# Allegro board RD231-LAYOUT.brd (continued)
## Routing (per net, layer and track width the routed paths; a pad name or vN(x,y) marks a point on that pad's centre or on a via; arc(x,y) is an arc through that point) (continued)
VCC12: length 11.2
  TOP w0.35: IC9.9 38.09,88.65 38.11,88.64 ; 38.11,88.64 38.4,88.53 ; 38.11,88.64 38.22,88.34 ; 38.11,88.64 38.35,88.39
  TOP w0.635: C109.1 39.12,87.63 ; 39.12,87.63 38.35,88.39 ; 39.12,87.63 38.61,87.12 C110.2 R116.1 38.61,82.61 37.28,81.28
DRVCC: length 55.1
  CONDUCTIVE3 w0.635: 64.64,43.94 61.98,43.94 58.22,40.19 ; 64.64,43.94 66.36,42.22 ; 64.64,43.94 66.93,46.23 ; 65.69,54.43 65.29,55.09 ; 65.69,54.43 65.02,54.83 ; 65.69,54.43 v1(65.12,54.99) ; 65.69,54.43 66.93,53.19 66.93,46.23 ; 58.22,40.19 v1(57.66,39.62) ; 58.22,40.19 57.82,39.53 ; 58.22,40.19 57.56,39.79 ; 70.94,44.51 69.22,46.23 66.93,46.23 ; 70.94,44.51 71.6,44.1 ; 70.94,44.51 71.34,43.84 ; 70.94,44.51 v1(71.5,43.94) ; 66.36,42.22 v1(66.93,41.66) ; 66.36,42.22 66.77,41.56 ; 66.36,42.22 67.03,41.82
  BOTTOM w0.35: 65.12,54.38 65.3,54.94 ; 65.12,54.38 v1(65.12,54.99) ; 65.12,54.38 65.12,52.5 ; 65.12,54.38 64.95,54.94 ; 65.62,43.07 65.49,42.58 ; 65.62,43.07 65.62,44.02 ; 65.62,43.07 65.76,42.58 ; 65.62,43.07 65.62,42.55
  BOTTOM w0.635: 65.62,42.55 65.62,42.07 66.04,41.66 66.46,41.66 ; 67.26,41.33 66.96,41.68 ; 67.26,41.33 v1(66.93,41.66) 66.46,41.66 ; 67.26,41.33 66.9,41.63 ; 67.26,41.33 68.45,40.13 C5.1 ; 57.65,39.66 57.19,39.62 ; 57.19,39.62 57.65,39.59 ; 57.19,39.62 D1.1 ; 57.19,39.62 v1(57.66,39.62) ; 66.46,41.66 66.93,41.62 ; 66.46,41.66 66.93,41.69 ; 71.5,43.9 71.97,43.94 ; 71.97,43.94 73.28,43.94 D2.1 ; 71.97,43.94 v1(71.5,43.94) ; 71.97,43.94 71.5,43.98
ISEN1: length 66.8
  TOP w0.35: R76.2 54.34,142.98 54.34,145.08 ; 54.16,145.64 54.34,145.08 ; 54.34,145.08 54.51,145.64 ; 54.34,145.08 v1(54.34,145.69) ; 53.77,101.04 v1(53.34,101.47) 53.34,102.08 ; 53.77,101.04 53.86,100.95 IC2.32 ; 53.77,101.04 53.5,101.56 ; 53.77,101.04 53.26,101.31 ; C48.1 55.37,104.52 53.34,102.49 53.34,102.08 ; 53.34,102.08 53.17,101.53 ; 53.34,102.08 53.51,101.53
  CONDUCTIVE3 w0.35: 54.65,145.57 54.34,144.75 ; 54.34,144.75 54.2,145.57 ; 54.34,144.75 v1(54.34,145.69) ; 54.34,144.75 54.37,145.57 ; 54.34,144.75 54.02,145.57 ; 54.34,144.75 54.34,144.15 54.86,143.62 54.86,110.87 55.63,110.11 55.63,107.57 53.34,105.28 53.34,102.42 ; 53.65,101.59 53.34,102.42 ; 53.34,102.42 53.03,101.59 ; 53.34,102.42 53.48,101.59 ; 53.34,102.42 v1(53.34,101.47) ; 53.34,102.42 53.3,101.59
ISEN1+: length 7.7
  TOP w0.35: IC2.33 53.36,100.18 52.45,101.09 52.45,102.23 52.7,102.49 52.7,103.12 53.21,103.63 C42.1 53.85,104.52 R70.2
ISEN2: length 112.6
  TOP w0.35: 58.34,100.51 57.83,100.24 ; 58.34,100.51 59.18,101.35 63.37,101.35 66.29,104.27 C50.1 ; 58.34,100.51 58.07,99.99 ; 58.34,100.51 v1(57.91,100.08) 57.3,100.08 ; v1(106.15,145.69) 106.15,145.08 ; 106.15,145.08 106.15,142.77 R77.2 ; 106.15,145.08 105.98,145.64 ; 106.15,145.08 106.32,145.64 ; 57.3,100.08 57.86,100.25 ; 57.3,100.08 57.86,99.9 ; 57.3,100.08 57.28,100.08 56.86,99.66 IC2.26
  CONDUCTIVE3 w0.35: 106.15,144.75 106.19,145.57 ; 106.15,144.75 106.46,145.57 ; 106.15,144.75 106.15,144.02 106.68,143.49 106.68,116.2 102.36,111.89 79.5,111.89 77.34,109.73 67.94,109.73 64.9,106.68 63.25,106.68 59.94,103.38 59.94,102.11 58.58,100.74 ; 106.15,144.75 105.84,145.57 ; 106.15,144.75 106.02,145.57 ; 106.15,144.75 v1(106.15,145.69) ; 58.09,100.06 58.58,100.74 ; 58.58,100.74 v1(57.91,100.08) ; 58.58,100.74 58.22,99.94 ; 58.58,100.74 57.77,100.38 ; 58.58,100.74 57.97,100.19
ISEN3: length 87.7
  TOP w0.35: 50.52,100.84 49.96,101.01 ; 50.52,100.84 49.96,100.67 ; 50.52,100.84 v1(49.91,100.84) 49.48,101.27 ; 50.52,100.84 51.18,100.84 52.36,99.66 IC2.35 ; 49.99,101 49.48,101.27 ; 49.48,101.27 47.75,103 C52.1 ; 49.48,101.27 49.75,100.75 ; 28.28,145.62 28.45,145.06 ; 28.45,145.06 28.45,143 R78.2 ; 28.45,145.06 v1(28.45,145.67) ; 28.45,145.06 28.62,145.62
  CONDUCTIVE3 w0.35: 50.58,101.5 49.97,100.95 ; 50.58,101.5 50.93,101.85 50.93,105.92 52.58,107.57 52.58,108.33 48.64,112.27 33.27,112.27 28.96,116.59 28.96,143.38 28.45,143.89 28.45,144.73 ; 50.58,101.5 50.09,100.82 ; 50.58,101.5 49.77,101.14 ; 50.58,101.5 50.21,100.7 ; 50.58,101.5 v1(49.91,100.84) ; 28.76,145.55 28.45,144.73 ; 28.45,144.73 28.31,145.55 ; 28.45,144.73 28.14,145.55 ; 28.45,144.73 28.49,145.55 ; 28.45,144.73 v1(28.45,145.67)
ISEN4: length 81.8
  TOP w0.35: 57.83,103.3 57.32,103.03 ; 57.83,103.3 58.67,104.14 C54.1 ; 57.83,103.3 v1(57.4,102.87) 56.97,102.44 ; 57.83,103.3 57.56,102.79 ; 80.24,145.08 80.24,142.85 R79.2 ; 80.24,145.08 v1(80.24,145.69) ; 80.24,145.08 80.07,145.64 ; 80.24,145.08 80.42,145.64 ; IC2.29 55.36,100.83 56.97,102.44 ; 57.24,102.95 56.97,102.44 ; 56.97,102.44 57.49,102.71
  CONDUCTIVE3 w0.35: 80.24,144.75 80.28,145.57 ; 80.24,144.75 v1(80.24,145.69) ; 80.24,144.75 79.93,145.57 ; 80.24,144.75 80.11,145.57 ; 80.24,144.75 80.56,145.57 ; 80.24,144.75 80.24,144.04 80.77,143.51 80.77,116.2 76.2,111.63 63.12,111.63 61.09,109.6 61.09,106.55 58.07,103.54 ; 58.07,103.54 v1(57.4,102.87) ; 58.07,103.54 57.27,103.17 ; 58.07,103.54 57.46,102.98 ; 58.07,103.54 57.71,102.73 ; 58.07,103.54 57.58,102.86
ISEN5: length 134.5
  TOP w0.35: 132.06,145.08 132.23,145.64 ; 132.06,145.08 131.89,145.64 ; 132.06,145.08 132.06,142.9 R80.2 ; 132.06,145.08 v1(132.06,145.69) ; 63.21,100.33 62.81,100.5 ; 63.21,100.33 62.81,100.16 ; 63.21,100.33 v1(62.74,100.33) 62.13,100.33 ; 63.21,100.33 63.25,100.33 66.55,103.63 67.06,103.63 67.82,104.39 C56.1 ; IC2.23 59.15,97.5 61.98,100.33 62.13,100.33 ; 62.68,100.5 62.13,100.33 ; 62.13,100.33 62.68,100.16
  CONDUCTIVE3 w0.35: 131.92,145.57 132.06,144.75 ; 132.06,144.75 131.75,145.57 ; 132.06,144.75 132.1,145.57 ; 132.06,144.75 132.06,144.02 132.59,143.49 132.59,116.2 126.75,110.36 81.41,110.36 77.98,106.93 66.55,106.93 62.74,103.12 62.74,101.27 ; 132.06,144.75 132.37,145.57 ; 132.06,144.75 v1(132.06,145.69) ; 62.74,101.27 v1(62.74,100.33) ; 62.74,101.27 63.05,100.45 ; 62.74,101.27 62.7,100.45 ; 62.74,101.27 62.87,100.45 ; 62.74,101.27 62.43,100.45
LGND: length 703.2
  TOP w0.3: 79.7,8.26 79.45,8 72.95,8 72.7,8.26 E2.4 73.08,13.72 79.32,13.72 E2.1
  TOP w0.35: 67.59,86.74 67.33,86.74 ; 67.59,86.74 v1(68.2,86.74) ; 67.59,86.74 68.15,86.91 ; 67.59,86.74 68.15,86.57 ; 67.33,86.74 66.84,86.6 ; 67.33,86.74 66.84,86.88 ; 67.33,86.74 66.8,86.74 ; IC9.11 v3(37.59,91.69) ; 70.94,97.07 70.39,96.9 ; 70.39,96.9 70.1,96.9 R26.1 ; 70.39,96.9 v1(70.99,96.9) ; 70.39,96.9 70.94,96.73
  TOP w0.635: 35.6,84.97 35.56,85.43 ; 35.56,85.43 v1(35.56,84.96) ; 35.56,85.43 C111.1 ; 35.56,85.43 35.52,84.97 ; 38.69,130.6 38.23,130.64 ; 38.69,130.6 v1(38.23,130.6) ; 38.69,130.6 38.23,130.57 ; 38.69,130.6 39.62,130.6 C61.2 ; 12.78,130.6 12.32,130.64 ; 12.78,130.6 12.32,130.57 ; 12.78,130.6 v1(12.32,130.6) ; 12.78,130.6 13.72,130.6 C60.2 ; 59.45,42.81 60.58,43.94 66.46,43.94 ; 59.45,42.81 v1(59.12,42.48) ; 59.45,42.81 59.09,42.51 ; 59.45,42.81 59.15,42.46 ; v1(90.04,130.6) 90.51,130.6 ; 90.51,130.6 90.05,130.64 ; 90.51,130.6 91.44,130.6 C62.2 ; 90.51,130.6 90.05,130.57 ; C42.2 51.69,104.27 52.32,104.9 C49.2 ; 69.82,94.39 69.52,94.03 ; 69.52,94.03 69.47,93.98 C31.2 ; 69.52,94.03 69.87,94.33 ; 69.52,94.03 v1(69.85,94.36) ; 68.88,101.08 69.34,101.04 ; 68.88,101.08 68.45,101.08 R65.1 ; 68.88,101.08 v1(69.34,101.08) ; 68.88,101.08 69.34,101.12 ; 64.14,130.57 64.6,130.6 ; 64.6,130.6 65.53,130.6 C84.2 ; 64.6,130.6 64.14,130.64 ; 64.6,130.6 v1(64.14,130.6) ; 62.27,84.08 62.23,84.54 ; 62.23,84.54 v1(62.23,84.07) ; 62.23,84.54 62.19,84.08 ; 62.23,84.54 R50.1 R51.1 ; 25.38,80.35 24.85,81.38 ; 24.85,81.38 24.7,81.53 S1.1 S1.2 S1.3 S1.4 S1.5 S1.6 S1.7 S1.8 ; 24.85,81.38 25.66,80.63 ; 24.85,81.38 v2(25.72,80.52) ; 24.85,81.38 25.89,80.86 ; 61.67,98.12 v1(61.34,97.79) ; 61.67,98.12 61.85,98.3 C32.2 ; 61.67,98.12 61.32,97.82 ; 61.67,98.12 61.37,97.77 ; 116.42,130.6 115.95,130.64 ; 116.42,130.6 115.95,130.57 ; 116.42,130.6 v1(115.95,130.6) ; 116.42,130.6 117.35,130.6 C85.2 ; v1(69.34,102.49) 69.81,102.49 ; 69.81,102.49 70.1,102.49 70.87,103.25 C46.2 C57.2 ; 69.81,102.49 69.35,102.45 ; 69.81,102.49 69.35,102.53 ; 66.46,43.94 v1(66.93,43.94) ; 66.46,43.94 66.93,43.9 ; 66.46,43.94 66.93,43.98 ; v1(45.47,87.38) 45.47,87.84 ; 45.47,87.84 C39.2 45.48,88.4 R66.1 ; 45.47,87.84 45.5,87.38 ; 45.47,87.84 45.43,87.38 ; C55.2 61.72,104.27 C45.2 ; 43.39,97.54 R40.1 ; 43.39,97.54 42.93,97.57 ; 43.39,97.54 42.93,97.5 ; 43.39,97.54 v1(42.93,97.54) 42.93,98 ; C110.1 R120.1 C109.2 41.66,88.14 39.12,90.68 v3(38.35,90.68) ; C43.2 62.74,104.39 63.25,104.9 C51.2 ; C108.1 R118.1 R119.1 32.51,90.44 R117.1 32.52,88.91 R114.1 R115.1 34.42,88.9 36.7,91.19 IC9.11 ; C40.2 R44.2 42.93,98.55 42.93,98 ; C53.2 50.8,104.52 C44.2 ; C37.2 65.02,88.39 v1(65.79,87.63) 66.42,87.63 66.8,87.25 C41.2 ; 42.93,98 42.89,97.54 ; 42.93,98 42.96,97.54 ; C122.1 C121.2 36.83,103.67 C114.1 40.01,103.38 41.02,102.36 41.02,93.6 39.12,91.69 v3(38.35,91.69)
  CONDUCTIVE2 w0.35: v1(57.02,106.17) 57.02,107.11 ; 57.02,107.11 57.33,106.29 ; 57.02,107.11 56.98,106.29 ; 57.02,107.11 57.02,107.44 46.74,117.73 46.74,125.17 ; 57.02,107.11 57.16,106.29 ; 57.02,107.11 56.71,106.29 ; 46.6,125.99 46.74,125.17 ; 46.74,125.17 47.05,125.99 ; 46.74,125.17 46.42,125.99 ; 46.74,125.17 v1(46.74,126.11) ; 46.74,125.17 46.77,125.99
  CONDUCTIVE3 w0.35: 71.11,96.59 71.94,96.9 ; 71.94,96.9 71.11,97.21 ; 71.94,96.9 71.11,96.94 ; 71.94,96.9 72.39,96.9 84.2,108.71 135.51,108.71 145.29,118.49 145.29,187.71 142.49,190.5 96.65,190.5 95.89,189.74 45.34,189.74 45.12,189.52 ; 71.94,96.9 v1(70.99,96.9) ; 71.94,96.9 71.11,96.76 ; 44.63,188.84 45.12,189.52 ; 45.12,189.52 v1(44.45,188.85) ; 45.12,189.52 44.75,188.71 ; 45.12,189.52 44.51,188.96 ; 45.12,189.52 44.31,189.15
  BOTTOM w0.3: 67.57,86.74 64.62,86.74 ; 67.57,86.74 68.13,86.79 ; 67.57,86.74 68.13,86.55 ; 67.57,86.74 v1(68.2,86.74) ; 67.57,86.74 68.13,86.94 ; 64.62,86.74 64.39,86.72 ; 64.62,86.74 64.39,86.77 ; 64.62,86.74 64.39,86.74 ; 66.3,43.94 66.24,43.94 66.12,44.06 ; 66.3,43.94 v1(66.93,43.94) ; 66.3,43.94 66.86,43.75 ; 66.3,43.94 66.86,43.99 ; 66.3,43.94 66.86,44.14
  BOTTOM w0.35: v3(64.77,49.53) 65.25,50.01 IC1.15 ; v3(64.77,49.53) 64.79,49.51 IC1.16 ; v3(64.77,49.53) 64.62,49.68 64.62,52.5 ; 47.34,126.11 46.79,126.28 ; 47.34,126.11 46.79,125.94 ; 47.34,126.11 51.45,126.11 R69.1 ; 47.34,126.11 v1(46.74,126.11) ; IC1.5 62.62,49.92 v3(62.23,49.53) 62.12,49.64 IC1.4 ; 57.45,105.74 57.18,106.26 ; 57.45,105.74 v1(57.02,106.17) ; 57.45,105.74 56.94,106.01 ; 57.45,105.74 57.78,105.41 62.61,105.41 64.39,103.63 64.39,98.04 61.09,94.74 61.09,90.04 64.39,86.74
  BOTTOM w0.635: 90.51,130.6 91.75,130.6 ; 90.51,130.6 v1(90.04,130.6) ; 90.51,130.6 90.05,130.64 ; 90.51,130.6 90.05,130.57 ; 69.89,94.36 69.85,94.83 ; 69.85,94.83 69.81,94.36 ; 69.85,94.83 C30.2 ; 69.85,94.83 v1(69.85,94.36) ; C28.2 R25.1 C9.2 52.79,50.8 ; v1(16.51,126.75) 16.51,126.11 18.54,124.08 25.53,124.08 29.72,128.27 31.62,128.27 ; v1(42.93,97.54) 43.39,97.54 ; 43.39,97.54 42.93,97.57 ; 43.39,97.54 42.93,97.5 ; 43.39,97.54 R40.1 R59.1 ; R11.1 63.63,60.37 ; R11.1 C13.2 ; R11.1 65.28,59.69 R8.1 66.81,58.15 C23.2 ; 63.63,60.37 v1(63.63,60.83) ; 63.63,60.37 63.66,60.83 ; 63.63,60.37 63.59,60.83 ; 67.26,43.61 72.39,38.48 86.74,38.48 88.65,40.39 93.85,40.39 ; 67.26,43.61 v1(66.93,43.94) ; 67.26,43.61 66.9,43.91 ; 67.26,43.61 66.96,43.97 ; v1(68.33,126.75) 68.33,126.11 70.36,124.08 77.34,124.08 81.53,128.27 v2(83.82,128.27) ; v1(68.2,37.21) 68.2,37.68 ; 68.2,37.68 68.2,37.86 C5.2 C1.2 65.42,38.11 R2.1 ; 68.2,37.68 68.24,37.21 ; 68.2,37.68 68.16,37.21 ; 64.6,130.6 64.14,130.64 ; 64.6,130.6 65.84,130.6 ; 64.6,130.6 v1(64.14,130.6) ; 64.6,130.6 64.14,130.57 ; v1(42.42,126.75) 42.42,126.36 44.7,124.08 53.47,124.08 55.12,125.73 55.12,127.76 55.63,128.27 v2(57.78,128.27) ; 52.79,50.8 v1(52.32,50.8) 51.86,50.8 ; 52.79,50.8 52.33,50.84 ; 52.79,50.8 52.33,50.76 ; 52.32,50.84 51.86,50.8 ; 51.86,50.8 51.31,50.8 50.55,50.04 50.55,48.26 51.05,47.75 C11.2 C15.2 ; 51.86,50.8 52.32,50.76 ; R4.1 71.77,48.77 C7.2 71.74,48.77 71.25,48.77 70.24,49.77 70.24,49.78 68.47,49.78 68.45,49.77 ; v1(115.95,130.6) 116.42,130.6 ; 116.42,130.6 119.97,130.6 v1(120.14,130.43) ; 116.42,130.6 115.95,130.64 ; 116.42,130.6 115.95,130.57 ; 38.69,130.6 39.93,130.6 ; 38.69,130.6 38.23,130.57 ; 38.69,130.6 v1(38.23,130.6) ; 38.69,130.6 38.23,130.64 ; 12.78,130.6 v1(12.32,130.6) ; 12.78,130.6 12.32,130.57 ; 12.78,130.6 14.02,130.6 ; 12.78,130.6 12.32,130.64 ; C3.2 58.93,26.8 ; 59.08,42.48 59.12,42.02 ; 59.12,42.02 59.12,39.56 57.4,37.85 48.64,37.85 ; 59.12,42.02 v1(59.12,42.48) ; 59.12,42.02 59.16,42.48 ; v2(109.86,128.27) 107.44,128.27 103.25,124.08 96.27,124.08 94.23,126.11 v1(94.23,126.75) ; v2(135.89,128.27) 133.35,128.27 129.16,124.08 122.17,124.08 120.14,126.11 v1(120.14,126.75)
  vias: v1(16.51,130.3) v1(16.51,129.16) v1(16.51,127.89) v1(42.42,130.3) v1(42.42,129.16) v1(42.42,127.89) v1(51.82,102.87) v1(61.72,102.87) v1(68.33,130.43) v1(68.33,129.16) v1(68.33,127.89) v1(94.23,130.43) v1(94.23,129.16) v1(94.23,127.89) v1(120.14,129.16) v1(120.14,127.89) v2(7.62,156.84) v2(7.62,154.94) v2(7.62,153.03) v2(7.62,151.13) v2(7.62,149.22) v2(7.62,147.32) v2(7.62,145.41) v2(7.62,143.51) v2(7.62,141.6) v2(7.62,139.7) v2(7.62,137.79) v2(7.62,135.76) v2(7.62,133.99) v2(7.62,132.21) v2(7.62,130.18) v2(7.62,128.27) v2(7.62,126.24) v2(7.62,124.46) v2(7.62,122.68) v2(9.53,156.84) v2(9.53,154.94) v2(9.53,153.03) v2(9.53,151.13) v2(9.53,149.22) v2(9.53,147.32) v2(9.53,145.41) v2(9.53,143.51) v2(9.53,141.6) v2(9.53,139.7) v2(9.53,137.79) v2(9.53,135.76) v2(9.53,133.99) v2(9.53,132.21) v2(9.53,130.18) v2(9.53,128.27) v2(9.53,126.24) v2(9.53,124.46) v2(9.53,122.68) v2(11.43,156.84) v2(11.43,154.94) v2(11.43,153.03) v2(11.43,151.13) v2(11.43,149.22) v2(11.43,147.32) v2(11.43,145.41) v2(11.43,143.51) v2(11.43,141.6) v2(11.43,139.7) v2(11.43,137.79) v2(11.43,135.76) v2(11.43,133.99) v2(11.43,132.21) v2(11.43,124.46) v2(11.43,122.68) v2(13.34,149.22) v2(13.34,147.32) v2(13.34,145.41) v2(13.34,143.51) v2(13.34,141.6) v2(13.34,139.7) v2(13.34,137.79) v2(13.34,135.76) v2(13.34,133.99) v2(13.34,132.21) v2(13.97,58.42) v2(13.97,48.26) v2(13.97,38.1) v2(13.97,27.94) v2(13.97,17.78) v2(13.97,7.62) v2(15.24,143.51) v2(15.24,141.6) v2(15.24,139.7) v2(15.24,137.79) v2(15.24,135.76) v2(15.24,133.99) v2(15.24,132.21) v2(17.14,135.76) v2(17.14,133.99) v2(17.14,132.21) v2(19.05,135.76) v2(19.05,133.99) v2(19.05,132.21) v2(24.13,58.42) v2(24.13,48.26) v2(24.13,38.1) v2(24.13,27.94) v2(24.13,17.78) v2(24.13,7.62) v2(31.75,149.22) v2(31.75,147.32) v2(31.75,145.41) v2(31.75,143.51) v2(31.75,141.6) v2(31.75,139.7) v2(31.75,137.79) v2(31.75,135.89) v2(31.75,133.99) v2(31.75,132.08) v2(31.75,130.18) v2(31.75,128.27) v2(31.75,126.36) v2(31.75,124.46) v2(31.75,122.56) v2(33.66,156.84) v2(33.66,154.94) v2(33.66,153.03) v2(33.66,151.13) v2(33.66,149.22) v2(33.66,147.32) v2(33.66,145.41) v2(33.66,143.51) v2(33.66,141.6) v2(33.66,139.7) v2(33.66,137.79) v2(33.66,135.89) v2(33.66,133.99) v2(33.66,132.08) v2(33.66,130.18) v2(33.66,128.27) v2(33.66,126.36) v2(33.66,124.46) v2(33.66,122.56) v2(35.56,156.84) v2(35.56,154.94) v2(35.56,153.03) v2(35.56,151.13) v2(35.56,149.22) v2(35.56,147.32) v2(35.56,145.41) v2(35.56,143.51) v2(35.56,141.6) v2(35.56,139.7) v2(35.56,137.79) v2(35.56,135.89) v2(35.56,133.99) v2(35.56,132.08) v2(35.56,130.18) v2(35.56,128.27) v2(35.56,126.36) v2(35.56,124.46) v2(35.56,122.56) v2(37.47,156.84) v2(37.47,154.94) v2(37.47,153.03) v2(37.47,151.13) v2(37.47,149.22) v2(37.47,147.32) v2(37.47,145.41) v2(37.47,143.51) v2(37.47,141.6) v2(37.47,139.7) v2(37.47,137.79) v2(37.47,135.76) v2(37.47,133.99) v2(37.47,132.21) v2(37.47,124.46) v2(37.47,122.56) v2(39.37,149.22) v2(39.37,147.32) v2(39.37,145.41) v2(39.37,143.51) v2(39.37,141.6) v2(39.37,139.7) v2(39.37,137.79) v2(39.37,135.76) v2(39.37,133.99) v2(39.37,132.21) v2(40.51,18.41) v2(41.27,143.51) v2(41.27,141.6) v2(41.27,139.7) v2(41.27,137.79) v2(41.27,135.76) v2(41.27,133.99) v2(41.27,132.21) v2(42.42,18.41) v2(43.18,135.76) v2(43.18,133.99) v2(43.18,132.21) v2(44.32,18.41) v2(45.09,135.76) v2(45.09,133.99) v2(45.09,132.21) v2(46.99,40.64) v2(46.99,38.73) v2(46.99,36.83) v2(46.99,34.92) v2(48.51,18.41) v2(48.9,40.64) v2(48.9,38.73) v2(48.9,36.83) v2(48.9,34.92) v2(50.42,18.41) v2(52.32,18.41) v2(54.23,18.41) v2(56.13,18.41) v2(57.78,149.22) v2(57.78,147.32) v2(57.78,145.41) v2(57.78,143.51) v2(57.78,141.6) v2(57.78,139.7) v2(57.78,137.79) v2(57.78,135.89) v2(57.78,133.99) v2(57.78,132.08) v2(57.78,130.18) v2(57.78,126.36) v2(57.78,124.46) v2(57.78,122.56) v2(59.69,156.84) v2(59.69,154.94) v2(59.69,153.03) v2(59.69,151.13) v2(59.69,149.22) v2(59.69,147.32) v2(59.69,145.41) v2(59.69,143.51) v2(59.69,141.6) v2(59.69,139.7) v2(59.69,137.79) v2(59.69,135.89) v2(59.69,133.99) v2(59.69,132.08) v2(59.69,130.18) v2(59.69,128.27) v2(59.69,126.36) v2(59.69,124.46) v2(59.69,122.56) v2(61.34,68.58) v2(61.34,66.67) v2(61.59,156.84) v2(61.59,154.94) v2(61.59,153.03) v2(61.59,151.13) v2(61.59,149.22) v2(61.59,147.32) v2(61.59,145.41) v2(61.59,143.51) v2(61.59,141.6) v2(61.59,139.7) v2(61.59,137.79) v2(61.59,135.89) v2(61.59,133.99) v2(61.59,132.08) v2(61.59,130.18) v2(61.59,128.27) v2(61.59,126.36) v2(61.59,124.46) v2(61.59,122.56) v2(62.87,72.39) v2(62.87,70.48) v2(63.25,68.58) v2(63.25,66.67) v2(63.5,156.84) v2(63.5,154.94) v2(63.5,153.03) v2(63.5,151.13) v2(63.5,149.22) v2(63.5,147.32) v2(63.5,145.41) v2(63.5,143.51) v2(63.5,141.6) v2(63.5,139.7) v2(63.5,137.79) v2(63.5,135.76) v2(63.5,133.99) v2(63.5,132.21) v2(63.5,124.46) v2(63.5,122.56) v2(64.77,72.39) v2(64.77,70.48) v2(65.41,149.22) v2(65.41,147.32) v2(65.41,145.41) v2(65.41,143.51) v2(65.41,141.6) v2(65.41,139.7) v2(65.41,137.79) v2(65.41,135.76) v2(65.41,133.99) v2(65.41,132.21) v2(67.31,143.51) v2(67.31,141.6) v2(67.31,139.7) v2(67.31,137.79) v2(67.31,135.76) v2(67.31,133.99) v2(67.31,132.21) v2(69.22,135.76) v2(69.22,133.99) v2(69.22,132.21) v2(71.12,135.76) v2(71.12,133.99) v2(71.12,132.21) v2(72.64,18.41) v2(74.55,18.41) v2(76.45,18.41) v2(78.36,18.41) v2(80.26,18.41) v2(81.28,77.09) v2(81.28,75.18) v2(81.28,73.28) v2(82.55,71.37) v2(83.19,77.09) v2(83.19,75.18) v2(83.19,73.28) v2(83.82,149.22) v2(83.82,147.32) v2(83.82,145.41) v2(83.82,143.51) v2(83.82,141.6) v2(83.82,139.7) v2(83.82,137.79) v2(83.82,135.89) v2(83.82,133.99) v2(83.82,132.08) v2(83.82,130.18) v2(83.82,126.36) v2(83.82,124.46) v2(83.82,122.56) v2(84.45,71.37) v2(84.45,18.41) v2(85.72,156.84) v2(85.72,154.94) v2(85.72,153.03) v2(85.72,151.13) v2(85.72,149.22) v2(85.72,147.32) v2(85.72,145.41) v2(85.72,143.51) v2(85.72,141.6) v2(85.72,139.7) v2(85.72,137.79) v2(85.72,135.89) v2(85.72,133.99) v2(85.72,132.08) v2(85.72,130.18) v2(85.72,128.27) v2(85.72,126.36) v2(85.72,124.46) v2(85.72,122.56) v2(86.36,18.41) v2(87.63,156.84) v2(87.63,154.94) v2(87.63,153.03) v2(87.63,151.13) v2(87.63,149.22) v2(87.63,147.32) v2(87.63,145.41) v2(87.63,143.51) v2(87.63,141.6) v2(87.63,139.7) v2(87.63,137.79) v2(87.63,135.89) v2(87.63,133.99) v2(87.63,132.08) v2(87.63,130.18) v2(87.63,128.27) v2(87.63,126.36) v2(87.63,124.46) v2(87.63,122.56) v2(88.27,18.41) v2(89.53,156.84) v2(89.53,154.94) v2(89.53,153.03) v2(89.53,151.13) v2(89.53,149.22) v2(89.53,147.32) v2(89.53,145.41) v2(89.53,143.51) v2(89.53,141.6) v2(89.53,139.7) v2(89.53,137.79) v2(89.53,135.76) v2(89.53,133.99) v2(89.53,132.21) v2(89.53,124.46) v2(89.53,122.56) v2(91.44,149.22) v2(91.44,147.32) v2(91.44,145.41) v2(91.44,143.51) v2(91.44,141.6) v2(91.44,139.7) v2(91.44,137.79) v2(91.44,135.76) v2(91.44,133.99) v2(91.44,132.21) v2(93.34,143.51) v2(93.34,141.6) v2(93.34,139.7) v2(93.34,137.79) v2(93.34,135.76) v2(93.34,133.99) v2(93.34,132.21) v2(94.61,40.64) v2(94.61,38.73) v2(94.61,36.83) v2(94.61,34.92) v2(95.25,135.76) v2(95.25,133.99) v2(95.25,132.21) v2(96.52,40.64) v2(96.52,38.73) v2(96.52,36.83) v2(96.52,34.92) v2(97.16,135.76) v2(97.16,133.99) v2(97.16,132.21) v2(105.41,58.42) v2(105.41,48.26) v2(105.41,38.1) v2(105.41,27.94) v2(105.41,17.78) v2(105.41,7.62) v2(109.86,149.22) v2(109.86,147.32) v2(109.86,145.41) v2(109.86,143.51) v2(109.86,141.6) v2(109.86,139.7) v2(109.86,137.79) v2(109.86,135.89) v2(109.86,133.99) v2(109.86,132.08) v2(109.86,130.18) v2(109.86,126.36) v2(109.86,124.46) v2(109.86,122.56) v2(111.76,156.84) v2(111.76,154.94) v2(111.76,153.03) v2(111.76,151.13) v2(111.76,149.22) v2(111.76,147.32) v2(111.76,145.41) v2(111.76,143.51) v2(111.76,141.6) v2(111.76,139.7) v2(111.76,137.79) v2(111.76,135.89) v2(111.76,133.99) v2(111.76,132.08) v2(111.76,130.18) v2(111.76,128.27) v2(111.76,126.36) v2(111.76,124.46) v2(111.76,122.56) v2(113.67,156.84) v2(113.67,154.94) v2(113.67,153.03) v2(113.67,151.13) v2(113.67,149.22) v2(113.67,147.32) v2(113.67,145.41) v2(113.67,143.51) v2(113.67,141.6) v2(113.67,139.7) v2(113.67,137.79) v2(113.67,135.89) v2(113.67,133.99) v2(113.67,132.08) v2(113.67,130.18) v2(113.67,128.27) v2(113.67,126.36) v2(113.67,124.46) v2(113.67,122.56) v2(115.57,156.84) v2(115.57,154.94) v2(115.57,153.03) v2(115.57,151.13) v2(115.57,149.22) v2(115.57,147.32) v2(115.57,145.41) v2(115.57,143.51) v2(115.57,141.6) v2(115.57,139.7) v2(115.57,137.79) v2(115.57,135.76) v2(115.57,133.99) v2(115.57,132.21) v2(115.57,124.46) v2(115.57,122.56) v2(115.57,58.42) v2(115.57,48.26) v2(115.57,38.1) v2(115.57,27.94) v2(115.57,17.78) v2(115.57,7.62) v2(117.47,149.22) v2(117.47,147.32) v2(117.47,145.41) v2(117.47,143.51) v2(117.47,141.6) v2(117.47,139.7) v2(117.47,137.79) v2(117.47,135.76) v2(117.47,133.99) v2(117.47,132.21) v2(119.38,143.51) v2(119.38,141.6) v2(119.38,139.7) v2(119.38,137.79) v2(119.38,135.76) v2(119.38,133.99) v2(119.38,132.21) v2(121.28,135.76) v2(121.28,133.99) v2(121.28,132.21) v2(123.19,135.76) v2(123.19,133.99) v2(123.19,132.21) v2(125.73,58.42) v2(125.73,48.26) v2(125.73,38.1) v2(125.73,27.94) v2(125.73,17.78) v2(125.73,7.62) v2(135.89,149.22) v2(135.89,147.32) v2(135.89,145.41) v2(135.89,143.51) v2(135.89,141.6) v2(135.89,139.7) v2(135.89,137.79) v2(135.89,135.89) v2(135.89,133.99) v2(135.89,132.08) v2(135.89,130.18) v2(135.89,126.36) v2(135.89,124.46) v2(135.89,122.56) v2(135.89,58.42) v2(135.89,48.26) v2(135.89,38.1) v2(135.89,27.94) v2(135.89,17.78) v2(135.89,7.62) v2(137.79,156.84) v2(137.79,154.94) v2(137.79,153.03) v2(137.79,151.13) v2(137.79,149.22) v2(137.79,147.32) v2(137.79,145.41) v2(137.79,143.51) v2(137.79,141.6) v2(137.79,139.7) v2(137.79,137.79) v2(137.79,135.89) v2(137.79,133.99) v2(137.79,132.08) v2(137.79,130.18) v2(137.79,128.27) v2(137.79,126.36) v2(137.79,124.46) v2(137.79,122.56) v2(139.7,156.84) v2(139.7,154.94) v2(139.7,153.03) v2(139.7,151.13) v2(139.7,149.22) v2(139.7,147.32) v2(139.7,145.41) v2(139.7,143.51) v2(139.7,141.6) v2(139.7,139.7) v2(139.7,137.79) v2(139.7,135.89) v2(139.7,133.99) v2(139.7,132.08) v2(139.7,130.18) v2(139.7,128.27) v2(139.7,126.36) v2(139.7,124.46) v2(139.7,122.56) v2(141.6,156.84) v2(141.6,154.94) v2(141.6,153.03) v2(141.6,151.13) v2(141.6,149.22) v2(141.6,147.32) v2(141.6,145.41) v2(141.6,143.51) v2(141.6,141.6) v2(141.6,139.7) v2(141.6,137.79) v2(141.6,135.89) v2(141.6,133.99) v2(141.6,132.08) v2(141.6,130.18) v2(141.6,128.27) v2(141.6,126.36) v2(141.6,124.46) v2(141.6,122.56) v3(36.83,91.69) v3(36.83,90.68) v3(37.59,90.68) v3(53.34,96.52) v3(53.34,95.25) v3(53.34,93.98) v3(54.61,96.52) v3(54.61,95.25) v3(54.61,93.98) v3(55.88,96.52) v3(55.88,95.25) v3(55.88,93.98) v3(62.23,48.26) v3(62.23,46.99) v3(63.5,49.53) v3(63.5,48.26) v3(63.5,46.99) v3(64.77,48.26) v3(64.77,46.99)
PG: length 46.8
  TOP w0.35: R67.2 47.24,99.56 47.24,97.39 48.13,96.5 IC2.40 ; R67.2 46.22,100.58 C40.1 ; R67.2 46.23,100.99 ; v1(46.23,101.6) 46.23,100.99 ; 46.23,100.99 46.4,101.55 ; 46.23,100.99 46.06,101.55 ; 37.08,86.51 v1(37.08,87.12) 37.51,87.55 ; 37.08,86.51 36.91,87.07 ; 37.08,86.51 R121.1 ; 37.08,86.51 37.26,87.07 ; 37.51,87.55 37.24,87.04 ; 37.51,87.55 37,87.28 ; 37.51,87.55 37.59,87.63 IC9.8
  CONDUCTIVE3 w0.35: v1(46.23,101.6) 45.29,101.6 ; 45.29,101.6 44.58,101.6 41.15,98.17 41.15,96.27 39.88,95 36.96,95 35.18,93.22 35.18,89.03 36.42,87.79 ; 45.29,101.6 46.11,101.56 ; 45.29,101.6 46.11,101.29 ; 45.29,101.6 46.11,101.91 ; 45.29,101.6 46.11,101.74 ; 36.42,87.79 36.78,86.98 ; 36.42,87.79 v1(37.08,87.12) ; 36.42,87.79 36.97,87.18 ; 36.42,87.79 37.22,87.43 ; 36.42,87.79 37.1,87.3
PWM1: length 53.6
  TOP w0.35: 54.36,101.76 54.53,102.31 ; 54.36,101.76 54.19,102.31 ; 54.36,101.76 v1(54.36,102.37) ; 54.36,101.76 IC2.31
  TOP w0.635: v1(38.23,129.16) 38.69,129.16 ; 38.69,129.16 39.5,129.16 C61.1 ; 38.69,129.16 38.23,129.12 ; 38.69,129.16 38.23,129.2
  CONDUCTIVE2 w0.35: 54.37,102.55 53.69,103.03 ; 53.69,103.03 54.5,102.67 ; 53.69,103.03 v1(54.36,102.37) ; 53.69,103.03 54.25,102.42 ; 53.69,103.03 53.47,103.26 53.47,108.2 44.7,116.97 42.16,116.97 39.37,119.76 39.37,128.02 38.89,128.49 ; 53.69,103.03 54.06,102.23 ; 38.21,128.98 38.89,128.49 ; 38.89,128.49 38.34,129.1 ; 38.89,128.49 38.53,129.3 ; 38.89,128.49 v1(38.23,129.16) ; 38.89,128.49 38.09,128.86
  BOTTOM w0.3: IC3.4 40.07,129.02 39.93,129.16 38.86,129.16 ; 38.86,129.16 v1(38.23,129.16) ; 38.86,129.16 38.29,129.35 ; 38.86,129.16 38.29,128.96 ; 38.86,129.16 38.29,129.11
PWM2: length 74.1
  TOP w0.35: 58.88,99.65 59.39,99.92 ; 58.88,99.65 57.93,98.7 IC2.25 ; 58.88,99.65 59.15,100.16 ; 58.88,99.65 v1(59.31,100.08)
  TOP w0.635: C62.1 91.31,129.16 90.51,129.16 ; 90.51,129.16 90.05,129.12 ; 90.51,129.16 90.05,129.2 ; 90.51,129.16 v1(90.04,129.16)
  CONDUCTIVE2 w0.35: 90.03,128.98 90.71,128.49 ; 90.71,128.49 89.91,128.86 ; 90.71,128.49 90.15,129.1 ; 90.71,128.49 v1(90.04,129.16) ; 90.71,128.49 91.19,128.02 91.19,117.86 89.28,115.95 65.53,115.95 60.83,111.25 60.83,104.9 59.31,103.38 59.31,101.02 ; 90.71,128.49 90.35,129.3 ; 59,100.19 59.31,101.02 ; 59.31,101.02 59.27,100.19 ; 59.31,101.02 v1(59.31,100.08) ; 59.31,101.02 59.62,100.19 ; 59.31,101.02 59.45,100.19
  BOTTOM w0.3: v1(90.04,129.16) 90.68,129.16 ; 90.68,129.16 90.11,129.35 ; 90.68,129.16 91.75,129.16 91.88,129.02 IC4.4 ; 90.68,129.16 90.11,128.96 ; 90.68,129.16 90.11,129.11
PWM3: length 78.4
  TOP w0.35: IC2.36 51.86,98.83 51.26,99.42 ; 51.26,99.42 v1(50.83,99.85) ; 51.26,99.42 50.75,99.69 ; 51.26,99.42 50.99,99.94
  TOP w0.635: 12.78,129.16 12.32,129.2 ; 12.78,129.16 12.32,129.12 ; 12.78,129.16 13.59,129.16 C60.1 ; 12.78,129.16 v1(12.32,129.16)
  CONDUCTIVE2 w0.35: 12.99,128.49 13.46,128.02 13.46,118.75 16.26,115.95 44.7,115.95 50.83,109.82 50.83,100.8 ; 12.99,128.49 12.31,128.98 ; 12.99,128.49 12.43,129.1 ; 12.99,128.49 v1(12.32,129.16) ; 12.99,128.49 12.62,129.3 ; 12.99,128.49 12.18,128.86 ; v1(50.83,99.85) 50.83,100.8 ; 50.83,100.8 50.97,99.97 ; 50.83,100.8 51.14,99.97 ; 50.83,100.8 50.79,99.97 ; 50.83,100.8 50.52,99.97
  BOTTOM w0.3: 12.95,129.16 14.02,129.16 14.16,129.02 IC5.4 ; 12.95,129.16 12.39,129.11 ; 12.95,129.16 12.39,128.96 ; 12.95,129.16 12.39,129.35 ; 12.95,129.16 v1(12.32,129.16)
PWM4: length 50.9
  TOP w0.35: 55.32,101.93 54.86,101.47 IC2.30 ; 55.32,101.93 v1(55.75,102.36) ; 55.32,101.93 55.84,102.2 ; 55.32,101.93 55.59,102.45
  TOP w0.635: 64.6,129.16 65.4,129.16 C84.1 ; 64.6,129.16 v1(64.14,129.16) ; 64.6,129.16 64.14,129.12 ; 64.6,129.16 64.14,129.2
  CONDUCTIVE2 w0.35: 64.44,129.3 64.8,128.49 ; 64.8,128.49 v1(64.14,129.16) ; 64.8,128.49 64.25,129.1 ; 64.8,128.49 65.28,128.02 65.28,117.98 59.31,112.01 59.31,104.78 58.17,103.63 57.02,103.63 56.42,103.03 ; 64.8,128.49 64.12,128.98 ; 64.8,128.49 64,128.86 ; 55.93,102.35 56.42,103.03 ; 56.42,103.03 56.06,102.22 ; 56.42,103.03 v1(55.75,102.36) ; 56.42,103.03 55.81,102.47 ; 56.42,103.03 55.62,102.67
  BOTTOM w0.3: 64.2,129.35 64.77,129.16 ; 64.77,129.16 64.2,129.11 ; 64.77,129.16 65.84,129.16 65.97,129.02 IC6.4 ; 64.77,129.16 v1(64.14,129.16) ; 64.77,129.16 64.2,128.96
PWM5: length 99.2
  TOP w0.35: 60.55,100.16 60.28,99.65 ; 60.28,99.65 v1(60.71,100.08) ; 60.28,99.65 58.63,98 IC2.24 ; 60.28,99.65 60.79,99.92
  TOP w0.635: 115.95,129.12 116.42,129.16 ; 116.42,129.16 115.95,129.2 ; 116.42,129.16 v1(115.95,129.16) ; 116.42,129.16 117.22,129.16 C85.1
  CONDUCTIVE2 w0.35: 61.02,100.19 60.71,101.02 ; 60.71,101.02 60.67,100.19 ; 60.71,101.02 v1(60.71,100.08) ; 60.71,101.02 60.39,100.19 ; 60.71,101.02 60.84,100.19 ; 60.71,101.02 60.71,103.38 61.72,104.39 61.72,110.24 66.55,115.06 114.17,115.06 116.97,117.86 116.97,128.14 116.62,128.49 ; 116.25,129.3 116.62,128.49 ; 116.62,128.49 v1(115.95,129.16) ; 116.62,128.49 115.81,128.86 ; 116.62,128.49 116.06,129.1 ; 116.62,128.49 115.94,128.98
  BOTTOM w0.3: IC7.4 117.79,129.02 117.65,129.16 116.58,129.16 ; 116.02,128.96 116.58,129.16 ; 116.58,129.16 116.02,129.35 ; 116.58,129.16 116.02,129.11 ; 116.58,129.16 v1(115.95,129.16)
SIGN6423: length 3.5
  TOP w0.635: R15.2 46.1,42.55 44.86,41.3
SIGN6492: length 6.7
  TOP w0.35: 60.58,96.52 60.56,96.5 IC2.21 ; 60.58,96.52 60.89,96.64 ; 60.58,96.52 60.83,96.77 ; 60.58,96.52 60.7,96.83
  TOP w0.635: R29.1 C32.1 60.83,96.77
SIGN6507: length 5.4
  TOP w0.35: IC2.17 62.74,94.5 R57.2
SIGN6508: length 1.5
  BOTTOM w0.35: C33.1 68.31,97.02 R31.1
SIGN6511: length 1.5
  TOP w0.35: C34.2 R33.2
SIGN6515: length 7.8
  TOP w0.35: IC2.13 59.14,92.5 61.72,89.92 R39.1 C37.1
SIGN6516: length 12.9
  TOP w0.35: IC2.20 64.76,96 65.02,96.27 65.02,98.17 66.55,99.69 R38.2 66.81,99.71 R65.2
SIGN6519: length 7.6
  TOP w0.35: IC2.43 46.48,95 R37.2 R40.2
SIGN6523: length 10.8
  TOP w0.35: IC2.10 56.36,89.82 57.91,88.27 59.18,88.27 60.71,86.74 R34.1 R50.2 R51.2
SIGN6527: length 8.9
  TOP w0.35: IC2.48 50.04,92.5 47.44,89.9 R66.2 46.98,89.92 C39.1 R45.1
SIGN6529: length 6.2
  TOP w0.35: IC2.46 48.64,93.5 47.72,92.58 45.85,92.58 R43.1
SIGN6530: length 5.7
  TOP w0.35: IC2.44 45.48,94.5 R42.1 45.47,94.5
SIGN6532: length 92
  TOP w0.35: v1(68.2,85.6) 67.59,85.6 ; 67.59,85.6 67.31,85.6 C41.1 R46.1 64.39,87.5 61.34,87.5 59.94,88.9 58.29,88.9 56.86,90.33 IC2.11 ; 67.59,85.6 68.15,85.43 ; 67.59,85.6 68.15,85.77
  CONDUCTIVE2 w0.3: 47.85,126.87 47.88,126.03 ; 47.88,126.03 47.55,126.87 ; 47.88,126.03 48,126.87 ; 47.88,126.03 v1(47.88,127) ; 47.88,126.03 48.21,126.87 ; 47.88,126.03 47.7,126.87 ; 47.88,126.03 47.88,125.6 47.66,125.39 ; 47.66,125.39 47.48,125.24 ; 47.66,125.39 47.5,125.22 ; 47.66,125.39 47.52,125.21
  CONDUCTIVE2 w0.35: 57.33,104.51 57.69,105.31 ; 57.69,105.31 57.08,104.76 ; 57.69,105.31 v1(57.02,104.65) ; 57.69,105.31 58.04,105.66 58.04,107.44 47.5,117.98 47.5,125.22 ; 57.69,105.31 57.2,104.63 ; 57.69,105.31 56.89,104.95
  BOTTOM w0.3: 64.01,86.11 64.24,86.11 ; 64.24,86.11 64.01,86.13 ; 64.24,86.11 66.69,86.11 ; 64.24,86.11 64.01,86.08 ; 66.93,86.13 66.69,86.11 ; 66.69,86.11 66.93,86.08 ; 66.69,86.11 66.93,86.11
  BOTTOM w0.35: 57.63,104.65 57.08,104.82 ; 57.63,104.65 62.36,104.65 63.63,103.38 63.63,98.3 60.33,95 60.33,89.79 64.01,86.11 ; 57.63,104.65 57.08,104.48 ; 57.63,104.65 v1(57.02,104.65) ; 48.49,127 51.56,127 R68.2 ; 48.49,127 47.93,126.83 ; 48.49,127 v1(47.88,127) ; 48.49,127 47.93,127.17 ; v1(68.2,85.6) 67.59,85.6 ; 67.59,85.6 67.44,85.6 66.93,86.11 ; 67.59,85.6 68.15,85.43 ; 67.59,85.6 68.15,85.77
SIGN6534: length 11.9
  TOP w0.35: IC2.18 66.3,95 C31.1 C38.1 R26.2
SIGN6540: length 8.4
  TOP w0.35: IC2.41 47.75,96 46.47,97.28 46.47,98.83 R67.1 46.22,99.06 R44.1
SIGN6613: length 2.8
  BOTTOM w0.635: 107.11,135.69 106.59,135.17 R90.2 ; 107.11,135.69 107.41,136.04 ; 107.11,135.69 107.47,135.99 ; 107.11,135.69 v1(107.44,136.02)
SIGN6624: length 2.8
  BOTTOM w0.635: 29.39,135.69 28.87,135.17 R93.2 ; 29.39,135.69 v1(29.72,136.02) ; 29.39,135.69 29.69,136.04 ; 29.39,135.69 29.74,135.99
SIGN6683: length 2.8
  BOTTOM w0.635: 133.02,135.69 133.37,135.99 ; 133.02,135.69 132.5,135.17 R100.2 ; 133.02,135.69 133.32,136.04 ; 133.02,135.69 v1(133.35,136.02)
SIGN6715: length 12.9
  TOP w0.35: IC2.27 56.36,99.92 57.4,100.97 57.78,100.97 58.8,101.98 62.99,101.98 64.26,103.25 C43.1 64.77,104.39 R71.2
SIGN6717: length 9.3
  TOP w0.35: IC2.34 52.86,99.92 50.8,101.98 49.78,101.98 48.64,103.12 C44.1 48.64,104.65 49.28,105.28 R72.2
SIGN6719: length 8.7
  TOP w0.35: R73.2 60.2,104.27 C45.1 57.53,101.6 57.15,101.6 55.86,100.31 IC2.28
SIGN6721: length 15.7
  TOP w0.35: IC2.22 59.41,97 61.72,99.31 63.12,99.31 66.67,102.87 68.45,102.87 69.34,103.76 C46.1 R74.2
SIGN6792: length 3.1
  TOP w0.35: C111.2 35.8,87.36 37.09,88.65 IC9.7
SIGN6793: length 7.8
  TOP w0.35: 38.1,93.74 38.09,93.73 IC9.2 ; 38.1,93.74 38.35,94.18 ; 38.1,93.74 38.54,93.98 ; 38.1,93.74 38.47,94.11
  TOP w0.635: 38.47,94.11 38.47,94.61 38.1,94.99 C112.1 38.09,95 38.09,98.78 L10.1
SIGN6794: length 7.9
  TOP w0.35: R115.2 34.8,88.14 35.58,88.14 36.59,89.15 IC9.6 ; R115.2 C113.1 ; R115.2 R114.2 R122.1
SIGN6796: length 5.3
  TOP w0.35: IC9.3 37.59,93.98 36.58,95 C108.2
SIGN6815: length 5.8
  TOP w0.35: R119.2 R118.2 34.42,93.85 36.83,93.85 37.09,93.59 IC9.4
SIGN6816: length 9.1
  TOP w0.35: 47.1,95.53 47.12,95.5 IC2.42 ; 47.1,95.53 v1(46.74,95.89) ; 47.1,95.53 46.9,95.96 ; 47.1,95.53 46.66,95.72
  BOTTOM w0.35: 46.74,95.28 46.74,95 46.23,94.49 R58.2 ; 46.74,95.28 46.91,95.83 ; 46.74,95.28 v1(46.74,95.89) ; 46.74,95.28 46.56,95.83
SIGN6820: length 52.9
  TOP w0.35: IC2.45 47.77,94 47.74,93.97 ; 47.74,93.97 v1(47.37,93.6) ; 47.74,93.97 47.29,93.76 ; 47.74,93.97 47.53,93.52 ; 73.41,95.66 R28.1 ; 73.41,95.66 v1(73.41,96.27) ; 73.41,95.66 73.58,96.21 ; 73.41,95.66 73.23,96.21
  BOTTOM w0.3: 63.5,85.45 63.73,85.47 ; 63.73,85.47 63.5,85.5 ; 63.73,85.47 63.5,85.47 ; 63.73,85.47 66.31,85.47 ; 66.55,85.5 66.31,85.47 ; 66.31,85.47 66.55,85.45 ; 66.31,85.47 66.55,85.47
  BOTTOM w0.35: 47.37,92.99 47.54,93.55 ; 47.37,92.99 47.2,93.55 ; 47.37,92.99 47.37,87.12 48.64,85.85 63.12,85.85 63.5,85.47 ; 47.37,92.99 v1(47.37,93.6) ; 73.41,95.66 73.58,96.21 ; 73.41,95.66 73.41,89.53 68.58,84.71 67.31,84.71 66.55,85.47 ; 73.41,95.66 73.23,96.21 ; 73.41,95.66 v1(73.41,96.27)
SIGN6828: length 2.7
  TOP w0.35: IC9.1 38.59,93.22 39.62,94.25 C112.2
SIGN6838: length 4.6
  TOP w0.35: R117.2 35.31,91.71 35.31,92.53 35.87,93.09 36.59,93.09 IC9.5
SIGN6946: length 12.3
  TOP w0.635: 56.56,42.55 57.02,42.51 ; 56.56,42.55 v1(57.02,42.55) ; 56.56,42.55 57.02,42.58 ; 56.56,42.55 R15.1
  BOTTOM w0.635: 59.05,45.09 59.05,44.58 57.35,42.87 ; 57.35,42.87 57,42.57 ; 57.35,42.87 57.05,42.52 ; 57.35,42.87 v1(57.02,42.55)
SIGN6947: length 38.1
  TOP w0.635: 29.84,43.73 29.88,44.19 ; 29.84,43.73 29.81,44.19 ; 29.84,43.73 R14.1 ; 29.84,43.73 v1(29.84,44.2)
  CONDUCTIVE3 w0.635: 52.42,46.58 52.01,45.92 ; 52.01,45.92 51.94,45.85 48.9,45.85 47.24,44.2 30.65,44.2 ; 52.01,45.92 52.68,46.32 ; 52.01,45.92 v1(52.58,46.48) ; 29.89,44.01 30.65,44.2 ; 30.65,44.2 29.89,44.38 ; 30.65,44.2 v1(29.84,44.2)
  BOTTOM w0.35: 56.77,48.01 57.3,48.01 ; 57.3,48.01 56.81,48.15 ; 57.3,48.01 IC1.42 ; 57.3,48.01 56.81,47.87
  BOTTOM w0.635: 53.04,46.48 v1(52.58,46.48) ; 53.04,46.48 52.58,46.52 ; 53.04,46.48 55.24,46.48 56.77,48.01 ; 53.04,46.48 52.58,46.44
SIGN6948: length 6.2
  BOTTOM w0.35: C19.1 52.58,42.67 53.38,41.87 R12.2 53.21,40.47 D1.2
SIGN6954: length 12.3
  BOTTOM w0.35: R25.2 C28.1 ; C28.1 55.84,53.85 57.15,52.54 57.15,51.15 57.78,50.51 IC1.47 ; C28.1 C27.2 R24.1 R23.1
SIGN6957: length 4.6
  BOTTOM w0.35: R10.2 63.12,55.62 IC1.6
SIGN6960: length 13.7
  BOTTOM w0.35: 64.12,42.15 64.12,42.68 ; 64.12,42.68 64.12,44.02 ; 64.12,42.68 63.99,42.19 ; 64.12,42.68 64.26,42.19 ; IC1.32 62.62,42.69 ; 62.62,42.69 62.76,42.2 ; 62.62,42.69 62.62,42.16 ; 62.62,42.69 62.49,42.2
  BOTTOM w0.635: 62.62,42.04 62.62,40.37 R6.1 R2.2 65.41,39.61 C1.1 ; 62.62,42.04 64.01,42.04 64.12,42.15 ; 62.62,42.04 62.62,42.16
SIGN6989: length 4.1
  BOTTOM w0.35: C13.1 63.62,56.64 IC1.7
SIGN6992: length 34.3
  CONDUCTIVE3 w0.35: 74.88,48.77 v1(75.82,48.77) ; 74.88,48.77 75.7,48.73 ; 74.88,48.77 75.7,49.08 ; 74.88,48.77 75.7,48.46 ; 74.88,48.77 73.41,48.77 66.17,56.01 64.52,56.01 62.61,54.1 61.59,54.1 61.25,54.45 ; 74.88,48.77 75.7,48.9 ; 61.25,54.45 60.69,55.06 ; 61.25,54.45 v1(60.58,55.12) ; 61.25,54.45 60.57,54.94 ; 61.25,54.45 60.88,55.26 ; 61.25,54.45 60.44,54.81
  BOTTOM w0.35: 75.77,48.94 75.21,48.77 ; 75.21,48.77 75.77,48.6 ; 75.21,48.77 v1(75.82,48.77) ; 75.21,48.77 R4.2 R3.1 ; IC1.2 61.12,54.57 61.01,54.69 ; 61.01,54.69 v1(60.58,55.12) ; 61.01,54.69 60.74,55.2 ; 61.01,54.69 60.49,54.96
SIGN7000: length 1.5
  BOTTOM w0.35: R9.1 C11.1
SIGN7001: length 5.2
  BOTTOM w0.35: R58.1 R59.2 R56.2 R35.1
SIGN7005: length 5
  BOTTOM w0.35: IC1.45 56.75,49.51 54.99,47.75 C15.1
SIGN7007: length 6.1
  BOTTOM w0.35: R9.2 C9.1 55.98,50.8 56.77,50.01 IC1.46
SIGN7059: length 28.9
  TOP w0.35: 78.84,52.98 v1(78.49,53.34) ; 78.84,52.98 78.87,52.96 80.94,52.96 L2.2 ; 78.84,52.98 78.65,53.41 ; 78.84,52.98 78.41,53.17
  BOTTOM w0.35: 70.07,47.65 69.58,47.51 ; 69.58,47.51 70.1,47.51 ; 69.58,47.51 70.07,47.37 ; 69.58,47.51 IC1.20 ; v1(78.49,53.34) 77.88,53.34 ; 77.88,53.34 R20.1 ; 77.88,53.34 78.43,53.17 ; 77.88,53.34 78.43,53.51
  BOTTOM w0.635: 81.44,41.79 81.41,42.25 ; 81.41,42.25 v1(81.41,41.78) ; 81.41,42.25 81.41,43.42 77.34,47.49 C20.2 76.71,47.51 70.1,47.51 ; 81.41,42.25 81.37,41.79
SIGN7062: length 5.7
  BOTTOM w0.35: R13.1 70.1,45.97 69.07,47.01 IC1.21
SIGN7068: length 15.6
  TOP w0.635: 70.44,48.51 73.91,48.51 76.96,45.47 76.96,43.47 R16.1 ; 70.44,48.51 v1(69.98,48.51) ; 70.44,48.51 69.98,48.55 ; 70.44,48.51 69.98,48.48
  BOTTOM w0.35: 69.55,48.08 v1(69.98,48.51) ; 69.55,48.08 70.06,48.35 ; 69.55,48.08 69.82,48.6 ; 69.55,48.08 69.47,48.01 IC1.19
SIGN7069: length 4.3
  BOTTOM w0.35: 76.7,45.97 C20.1 ; 76.7,45.97 R13.2 ; 76.7,45.97 76.58,45.86 D2.2
SIGN7071: length 25.6
  BOTTOM w0.35: 68.16,45.5 68.18,45.32 ; 68.16,45.5 68.16,45.51 IC1.24 ; 68.16,45.5 68.33,45.34 ; 68.16,45.5 68.34,45.48
  BOTTOM w0.635: R17.1 86.19,39.5 72.9,39.5 68.33,44.07 68.33,45.34
SIGN7074: length 2.5
  BOTTOM w0.635: v1(92.48,41.66) 92.25,41.89 ; 92.25,41.89 92.51,41.69 ; 92.25,41.89 92.23,41.91 R17.2 ; 92.25,41.89 92.46,41.63
SIGN7078: length 6.3
  BOTTOM w0.35: R12.1 55.79,43.98 57.53,45.72 57.53,46.61 57.93,47.01 IC1.40
SIGN7084: length 10.6
  BOTTOM w0.35: IC1.35 61.12,42.6 ; 61.12,42.6 61.12,42.07 ; 61.12,42.6 60.99,42.11 ; 61.12,42.6 61.26,42.11
  BOTTOM w0.635: 61.12,42.07 61.12,39.28 61.21,39.19 R1.2 59,36.83 C3.1
SIGN7088: length 32.6
  CONDUCTIVE3 w0.35: 62.3,55.09 62.78,55.77 ; 62.78,55.77 63.66,56.64 66.93,56.64 71.09,52.48 ; 62.78,55.77 61.98,55.41 ; 62.78,55.77 v1(62.12,55.1) ; 62.78,55.77 62.42,54.97 ; 62.78,55.77 62.17,55.21 ; 71.09,52.48 71.64,51.87 ; 71.09,52.48 71.89,52.12 ; 71.09,52.48 v1(71.75,51.82) ; 71.09,52.48 71.45,51.68 ; 71.09,52.48 71.77,52
  BOTTOM w0.35: IC1.3 61.62,54.61 61.69,54.67 ; 61.69,54.67 v1(62.12,55.1) ; 61.69,54.67 62.2,54.94 ; 61.69,54.67 61.96,55.19 ; 71.81,51.99 72.36,51.82 ; 72.36,51.82 v1(71.75,51.82) ; 72.36,51.82 71.81,51.64 ; 72.36,51.82 R7.2 R3.2 73.03,50.28 C7.1 71.53,50.51 IC1.14
SIGN7089: length 30.4
  CONDUCTIVE3 w0.35: 66.09,57.66 69.72,57.66 74.9,52.48 ; 66.09,57.66 65.27,57.7 ; 66.09,57.66 v1(65.15,57.66) ; 66.09,57.66 65.27,57.52 ; 66.09,57.66 65.27,57.35 ; 66.09,57.66 65.27,57.97 ; 74.9,52.48 75.45,51.87 ; 74.9,52.48 75.58,52 ; 74.9,52.48 v1(75.56,51.82) ; 74.9,52.48 75.26,51.68 ; 74.9,52.48 75.7,52.12
  BOTTOM w0.35: v1(75.56,51.82) 74.96,51.82 ; 74.96,51.82 R7.1 ; 74.96,51.82 75.51,51.64 ; 74.96,51.82 75.51,51.99 ; 64.12,52.5 64.12,55.37 65.15,56.4 ; 65.15,57.05 65.32,57.6 ; 65.15,57.05 64.98,57.6 ; 65.15,57.05 65.15,56.4 ; 65.15,57.05 v1(65.15,57.66) ; 65.15,56.4 66.56,56.4 R8.2
SIGN7090: length 6.8
  BOTTOM w0.35: 65.62,52.5 65.62,53.94 65.64,53.95 ; 65.64,53.95 65.64,53.96 C23.1 R22.2 ; 65.64,53.95 65.62,53.95
SIGN7092: length 10
  BOTTOM w0.35: R21.1 R18.2 58.04,58.42 C17.1 58.93,55.75 58.93,54.36 59.69,53.59 59.69,51.01 IC1.48
SIGN7094: length 9.3
  BOTTOM w0.35: IC1.13 69.3,51.01 71.63,53.34 C18.2 R19.1 R20.2
SIGN7098: length 7.5
  TOP w0.35: IC2.14 60.2,93 62.01,91.19 C36.2 R36.1
SIGN7099: length 10.1
  TOP w0.35: IC2.15 60.71,93.5 61.5,92.71 C36.1 R36.2 C35.2 R33.1
SIGN7100: length 28.2
  TOP w0.35: C35.1 66.29,91.19 C34.1 66.29,89.25 ; 62.18,93.9 61.62,93.73 ; 61.62,93.73 62.18,93.55 ; 61.62,93.73 v1(62.23,93.73) ; 61.62,93.73 61.62,93.73 61.34,94 IC2.16 ; 66.29,89.25 66.12,88.7 ; 66.29,89.25 66.47,88.7 ; 66.29,89.25 v1(66.29,88.65)
  BOTTOM w0.35: C33.2 R30.1 68.58,94.23 69.47,93.34 69.47,91.82 66.72,89.08 ; 62.23,93.12 62.23,92.71 65.86,89.08 ; 62.23,93.12 62.06,93.67 ; 62.23,93.12 v1(62.23,93.73) ; 62.23,93.12 62.4,93.67 ; 66.45,88.56 66.72,89.08 ; 66.72,89.08 v1(66.29,88.65) 65.86,89.08 ; 66.72,89.08 66.21,88.81 ; 65.86,89.08 66.13,88.56 ; 65.86,89.08 66.38,88.81
SIGN7102: length 6.5
  TOP w0.35: 65.61,94.15 65.05,93.98 ; 65.05,93.98 v1(65.66,93.98) ; 65.05,93.98 65.61,93.81 ; 65.05,93.98 R57.1
  BOTTOM w0.35: 65.58,93.82 66.09,93.55 ; 66.09,93.55 65.82,94.06 ; 66.09,93.55 v1(65.66,93.98) ; 66.09,93.55 66.8,92.84 R49.2 66.81,92.71 R30.2
SIGN7103: length 2.8
  BOTTOM w0.35: R32.1 65.29,95.52 R31.2 R49.1
SIGN7104: length 25.9
  TOP w0.35: 69.56,99.65 69.29,99.14 ; 69.29,99.14 R48.2 C38.2 66.42,98.3 65.79,97.66 65.79,96.01 65.27,95.5 IC2.19 ; 69.29,99.14 v1(69.72,99.57) ; 69.29,99.14 69.81,99.41
  BOTTOM w0.35: 69.12,99.57 67.82,99.57 R32.2 ; 69.12,99.57 69.67,99.4 ; 69.12,99.57 v1(69.72,99.57) 69.72,98.96 ; 69.12,99.57 69.67,99.74 ; 69.72,98.96 69.72,97.16 C30.1 ; 69.72,98.96 69.55,99.51 ; 69.72,98.96 69.9,99.51
SIGN7120: length 10
  TOP w0.635: v1(40.26,124.97) 40.49,124.74 ; 40.49,124.74 40.51,124.71 43.65,124.71 R85.1 ; 40.49,124.74 40.29,124.99 ; 40.49,124.74 40.24,124.94
  BOTTOM w0.635: 40.26,125.43 v1(40.26,124.97) ; 40.26,125.43 40.3,124.97 ; 40.26,125.43 40.26,126.44 40.89,127.08 40.89,127.13 ; 40.26,125.43 40.22,124.97
SIGN7121: length 2.1
  TOP w0.635: R85.2 47.71,122.77 Q5.4
SIGN7122: length 2.7
  BOTTOM w0.635: v1(55.63,129.92) 55.63,129.88 55.32,129.58 ; 55.32,129.58 54.99,129.25 R86.2 ; 55.32,129.58 55.65,129.89 ; 55.32,129.58 55.6,129.94
SIGN7123: length 6.9
  TOP w0.635: R82.1 38.23,126.58 38.23,127.42 ; 38.19,127.89 38.23,127.42 ; 38.23,127.42 v1(38.23,127.89) ; 38.23,127.42 38.27,127.89
  BOTTOM w0.3: 38.86,127.89 38.29,127.84 ; 38.86,127.89 38.29,127.69 ; 38.86,127.89 39.93,127.89 40.07,128.02 IC3.2 ; 38.86,127.89 v1(38.23,127.89) ; 38.86,127.89 38.29,128.08
SIGN7124: length 4.5
  TOP w0.635: R82.2 41.19,125.73 43.69,125.73 44.07,126.11 C69.1
SIGN7125: length 2.8
  BOTTOM w0.635: 55.3,135.69 55.65,135.99 ; 55.3,135.69 v1(55.63,136.02) ; 55.3,135.69 55.6,136.04 ; 55.3,135.69 54.78,135.17 R87.2
SIGN7126: length 12.5
  BOTTOM w0.635: 43.94,129.92 43.94,129.97 44.58,130.6 53.35,130.6 R86.1 R87.1
SIGN7129: length 10
  TOP w0.635: 92.31,124.74 92.33,124.71 95.47,124.71 R88.1 ; 92.31,124.74 v1(92.08,124.97) ; 92.31,124.74 92.05,124.94 ; 92.31,124.74 92.1,124.99
  BOTTOM w0.635: 92.11,124.97 92.08,125.43 ; 92.08,125.43 92.04,124.97 ; 92.08,125.43 v1(92.08,124.97) ; 92.08,125.43 92.08,126.44 92.71,127.08 92.71,127.13
SIGN7130: length 6.9
  TOP w0.635: R83.1 90.04,126.58 90.04,127.42 ; v1(90.04,127.89) 90.04,127.42 ; 90.04,127.42 90.08,127.89 ; 90.04,127.42 90,127.89
  BOTTOM w0.3: v1(90.04,127.89) 90.68,127.89 ; 90.68,127.89 90.11,127.84 ; 90.68,127.89 91.75,127.89 91.88,128.02 IC4.2 ; 90.68,127.89 90.11,128.08 ; 90.68,127.89 90.11,127.69
SIGN7131: length 4.5
  TOP w0.635: R83.2 93,125.73 95.5,125.73 95.88,126.11 C70.1
SIGN7132: length 2.1
  TOP w0.635: Q7.4 99.52,122.77 R88.2
SIGN7135: length 12.4
  BOTTOM w0.635: R90.1 R89.1 105.17,130.6 96.27,130.6 95.76,130.1 95.76,130.05
SIGN7136: length 1.8
  BOTTOM w0.635: R89.2 106.81,129.25 107.44,129.88 v1(107.44,129.92)
SIGN7139: length 10
  TOP w0.635: R91.1 17.74,124.71 14.61,124.71 14.58,124.74 ; 14.58,124.74 14.38,124.99 ; 14.58,124.74 14.33,124.94 ; 14.58,124.74 v1(14.35,124.97)
  BOTTOM w0.635: 14.35,125.43 14.35,126.44 14.99,127.08 14.99,127.13 ; 14.35,125.43 14.31,124.97 ; 14.35,125.43 v1(14.35,124.97) ; 14.35,125.43 14.39,124.97
SIGN7140: length 2.1
  TOP w0.635: Q9.4 21.8,122.77 R91.2
SIGN7142: length 6.9
  TOP w0.635: R84.1 12.32,126.58 12.32,127.42 ; 12.28,127.89 12.32,127.42 ; 12.32,127.42 v1(12.32,127.89) ; 12.32,127.42 12.36,127.89
  BOTTOM w0.3: 12.39,127.69 12.95,127.89 ; 12.95,127.89 14.02,127.89 14.16,128.02 IC5.2 ; 12.95,127.89 12.39,128.08 ; 12.95,127.89 v1(12.32,127.89) ; 12.95,127.89 12.39,127.84
SIGN7143: length 4.5
  TOP w0.635: R84.2 15.28,125.73 17.78,125.73 18.16,126.11 C71.1
SIGN7144: length 12.6
  BOTTOM w0.635: 18.03,129.92 18.03,130.1 18.54,130.6 27.44,130.6 R92.1 R93.1
SIGN7147: length 2.1
  TOP w0.635: Q14.4 73.62,122.77 R101.2
SIGN7148: length 9.9
  TOP w0.635: 66.4,124.74 66.2,124.99 ; 66.4,124.74 v1(66.17,124.97) ; 66.4,124.74 66.14,124.94 ; 66.4,124.74 66.42,124.71 69.56,124.71 R101.1
  BOTTOM w0.635: 66.17,125.43 v1(66.17,124.97) ; 66.17,125.43 66.2,124.97 ; 66.17,125.43 66.13,124.97 ; 66.17,125.43 66.17,126.44 66.72,127 66.8,127
SIGN7149: length 6.9
  TOP w0.635: 64.14,127.42 64.17,127.89 ; 64.14,127.42 64.1,127.89 ; 64.14,127.42 64.14,126.58 R94.1 ; 64.14,127.42 v1(64.14,127.89)
  BOTTOM w0.3: IC6.2 65.97,128.02 65.84,127.89 64.77,127.89 ; 64.2,127.69 64.77,127.89 ; 64.77,127.89 64.2,128.08 ; 64.77,127.89 v1(64.14,127.89) ; 64.77,127.89 64.2,127.84
SIGN7150: length 4.5
  TOP w0.635: C93.1 69.98,126.11 69.6,125.73 67.09,125.73 R94.2
SIGN7151: length 2.7
  BOTTOM w0.635: 81.23,129.58 81.53,129.88 v1(81.53,129.92) ; 81.23,129.58 81.56,129.89 ; 81.23,129.58 81.5,129.94 ; 81.23,129.58 80.9,129.25 R97.2
SIGN7152: length 2.8
  BOTTOM w0.635: 81.21,135.69 80.68,135.17 R98.2 ; 81.21,135.69 81.5,136.04 ; 81.21,135.69 v1(81.53,136.02) ; 81.21,135.69 81.56,135.99
SIGN7153: length 12.6
  BOTTOM w0.635: R98.1 R97.1 79.26,130.6 70.36,130.6 69.85,130.1 69.85,129.92
SIGN7156: length 2.7
  BOTTOM w0.635: v1(133.35,129.92) 133.02,129.59 ; 133.02,129.59 133.32,129.95 ; 133.02,129.59 133.37,129.89 ; 133.02,129.59 132.68,129.25 R99.2
SIGN7157: length 12.5
  BOTTOM w0.635: 121.67,130.05 121.67,130.18 122.05,130.56 131.03,130.56 R99.1 R100.1
SIGN7158: length 2.1
  TOP w0.635: R102.2 125.43,122.77 Q16.4
SIGN7159: length 10
  TOP w0.635: 118.21,124.74 118.01,124.99 ; 118.21,124.74 118.24,124.71 121.37,124.71 R102.1 ; 118.21,124.74 117.96,124.94 ; 118.21,124.74 v1(117.98,124.97)
  BOTTOM w0.635: 117.98,125.43 v1(117.98,124.97) ; 117.98,125.43 117.94,124.97 ; 117.98,125.43 117.98,126.44 118.62,127.08 118.62,127.13 ; 117.98,125.43 118.02,124.97
SIGN7160: length 6.9
  TOP w0.635: 115.95,127.42 115.95,126.58 R95.1 ; 115.95,127.42 v1(115.95,127.89) ; 115.95,127.42 115.91,127.89 ; 115.95,127.42 115.99,127.89
  BOTTOM w0.3: 116.02,128.08 116.58,127.89 ; 116.58,127.89 116.02,127.84 ; 116.58,127.89 117.65,127.89 117.79,128.02 IC7.2 ; 116.58,127.89 v1(115.95,127.89) ; 116.58,127.89 116.02,127.69
SIGN7161: length 4.5
  TOP w0.635: C94.1 121.79,126.11 121.41,125.73 118.91,125.73 R95.2
SIGN7182: length 14
  TOP w0.35: IC9.10 38.59,89.68 39.01,89.26 ; 39.01,89.26 39.39,88.88 v1(39.39,88.79) ; 39.01,89.26 39.49,88.94 ; 39.01,89.26 39.22,88.73 ; R116.2 R120.2 42.06,84.58 ; 42.06,84.58 42.62,84.41 ; 42.06,84.58 v1(42.67,84.58) ; 42.06,84.58 42.62,84.75
  BOTTOM w0.35: 39.8,88.34 42.67,85.47 42.67,85.19 ; 39.8,88.34 39.3,88.63 ; 39.8,88.34 39.55,88.87 ; 39.8,88.34 39.39,88.76 v1(39.39,88.79) ; 42.84,84.64 42.67,85.19 ; 42.67,85.19 v1(42.67,84.58) ; 42.67,85.19 42.5,84.64
SIGN7185: length 6.1
  TOP w0.35: R55.2 55.36,88.91 IC2.8
SIGN7189: length 5.3
  TOP w0.35: R53.2 54.36,86.86 IC2.6
SIGN7191: length 5.5
  TOP w0.35: IC2.5 53.86,87.39 R52.2
SIGN7192: length 5.7
  TOP w0.35: IC2.7 54.86,87.89 R54.2
SIGN7193: length 5.9
  TOP w0.35: R63.2 53.36,88.41 IC2.4
SIGN7195: length 6.4
  TOP w0.35: R62.2 52.86,89.44 IC2.3
SIGN7198: length 7.2
  TOP w0.35: R60.2 51.86,91.48 IC2.1
SIGN7199: length 6.8
  TOP w0.35: R61.2 52.36,90.46 IC2.2
SIGN7201: length 7.2
  TOP w0.35: IC2.9 55.86,89.43 57.66,87.63 58.8,87.63 59.18,87.25 R64.2
SIGN7202: length 49.1
  TOP w0.35: 59.18,84.68 v1(59.18,84.07) ; 59.18,84.68 59.01,84.13 ; 59.18,84.68 59.35,84.13 ; 59.18,84.68 R64.1 ; 74.42,92.71 73.91,92.71 R27.1 ; 74.42,92.71 75.91,93.19 ; 74.42,92.71 75.91,92.49 ; 74.42,92.71 75.91,92.84 ; 74.42,92.71 75.91,92.31 ; 74.42,92.71 75.91,92.66 ; 74.42,92.71 75.91,93.01 ; 74.42,92.71 CN1.1 ; 74.42,92.71 75.91,92.06 ; 74.42,92.71 75.91,93.36
  BOTTOM w0.3: 63.35,84.84 65.93,84.84 ; 63.35,84.84 63.12,84.81 ; 63.35,84.84 63.12,84.84 ; 63.35,84.84 63.12,84.86 ; 65.93,84.84 66.16,84.86 ; 65.93,84.84 66.16,84.81 ; 65.93,84.84 66.17,84.84
  BOTTOM w0.35: 63.12,84.84 62.99,84.96 60.07,84.96 59.61,84.5 ; 59.34,83.99 59.61,84.5 ; 59.61,84.5 v1(59.18,84.07) ; 59.61,84.5 59.1,84.23 ; 76.12,92.33 76.2,91.38 ; 76.2,91.38 75.6,92.33 ; 76.2,91.38 75.95,92.33 ; 76.2,91.38 76.2,91.31 68.83,83.95 67.06,83.95 66.17,84.84 ; 76.2,91.38 76.3,92.33 ; 76.2,91.38 CN1.1 ; 76.2,91.38 75.77,92.33 ; 76.2,91.38 76.8,92.33 ; 76.2,91.38 76.47,92.33
SIGN7205: length 1.3
  BOTTOM w0.635: R5.1 R6.2
SIGN7206: length 1.5
  BOTTOM w0.35: R69.2 53.34,125.73 R68.1
SIGN7208: length 1.5
  BOTTOM w0.35: R11.2 R10.1
SIGN7217: length 7.3
  TOP w0.35: R39.2 62.23,88.39 58.82,91.8 IC2.12
SIGN7218: length 6.3
  TOP w0.35: IC2.47 49.15,93 47.59,91.44 R41.1
VID0: length 56.4
  TOP w0.35: R55.1 57.66,83.82 52.83,78.99 48.26,78.99 42.42,73.15 22.35,73.15 17.27,78.23 17.27,82.04 16.51,82.8 S1.16 R113.1
VID1: length 56.2
  TOP w0.35: R112.1 S1.15 16.76,85.34 18.03,84.07 18.03,78.74 22.86,73.91 41.91,73.91 47.75,79.76 52.07,79.76 56.13,83.82 R54.1
VID2: length 55.8
  TOP w0.35: R53.1 54.61,83.82 51.31,80.52 47.24,80.52 41.4,74.68 23.37,74.68 18.8,79.25 18.8,85.85 16.76,87.88 S1.14 R111.1
VID3: length 55.4
  TOP w0.35: R52.1 53.09,83.82 50.55,81.28 46.74,81.28 40.89,75.44 23.88,75.44 19.56,79.76 19.56,87.63 16.76,90.42 S1.13 R110.1
VID4: length 54.9
  TOP w0.35: R63.1 51.56,84.07 49.53,82.04 46.23,82.04 40.39,76.2 24.38,76.2 20.32,80.26 20.32,89.41 16.76,92.96 S1.12 R109.1
VID5: length 54.6
  TOP w0.35: R108.1 S1.11 16.76,95.5 21.08,91.19 21.08,80.77 24.89,76.96 39.88,76.96 45.72,82.8 48.77,82.8 50.04,84.07 R62.1
VID6: length 54.2
  TOP w0.35: R107.1 S1.10 16.76,98.04 21.84,92.96 21.84,81.28 25.4,77.72 39.37,77.72 45.21,83.57 48.01,83.57 48.51,84.07 R61.1
VID7: length 53.3
  TOP w0.35: R60.1 46.48,84.58 44.96,84.58 38.86,78.49 25.91,78.49 22.61,81.79 22.61,94.74 16.76,100.58 S1.9 R106.1
VP_1R2_VOUT: length 655
  TOP w0.35: v1(54.61,107.95) 54.18,107.52 ; 54.18,107.52 54.69,107.79 ; 54.18,107.52 54.45,108.03 ; 54.18,107.52 53.85,107.19 R70.1 ; 130.68,145.06 130.85,145.62 ; 130.68,145.06 130.68,144.27 130.3,143.89 125.09,143.89 L8.2 ; 130.68,145.06 130.51,145.62 ; 130.68,145.06 v1(130.68,145.67) ; 78.69,145.62 78.87,145.06 ; 78.87,145.06 79.04,145.62 ; 78.87,145.06 78.87,144.57 78.21,143.91 73.03,143.91 L7.2 ; 78.87,145.06 v1(78.87,145.67) ; C49.1 R70.1 ; R70.1 C48.2 ; R72.1 C52.2 ; R72.1 C53.1 ; R72.1 49.28,107.57 49.66,107.95 50.95,107.95 ; 104.78,145.06 104.78,144.4 104.14,143.76 99.06,143.76 L5.2 ; 104.78,145.06 104.95,145.62 ; 104.78,145.06 104.6,145.62 ; 104.78,145.06 v1(104.78,145.67) ; 70.39,98.3 70.94,98.13 ; 70.39,98.3 R48.1 ; 70.39,98.3 70.94,98.47 ; 70.39,98.3 v1(70.99,98.3) ; 50.95,107.95 51.51,108.12 ; 50.95,107.95 51.51,107.78 ; 50.95,107.95 v1(51.56,107.95) ; R74.1 C57.1 ; R74.1 69.34,107.7 69.09,107.95 68.43,107.95 ; R74.1 C56.2 ; v1(64.77,107.95) 64.77,107.34 ; 64.77,107.34 64.6,107.9 ; 64.77,107.34 R71.1 ; 64.77,107.34 64.94,107.9 ; R73.1 C54.2 ; R73.1 C55.1 ; R73.1 60.07,107.06 60.07,107.34 ; v1(67.82,107.95) 68.43,107.95 ; 68.43,107.95 67.87,108.12 ; 68.43,107.95 67.87,107.78 ; 52.79,145.62 52.96,145.06 ; 52.96,145.06 v1(52.96,145.67) ; 52.96,145.06 52.96,144.7 52.18,143.91 46.99,143.91 L4.2 ; 52.96,145.06 53.13,145.62 ; R71.1 C50.2 ; R71.1 C51.1 ; 59.9,107.9 60.07,107.34 ; 60.07,107.34 60.24,107.9 ; 60.07,107.34 v1(60.07,107.95) ; 26.88,145.62 27.05,145.06 ; 27.05,145.06 27.22,145.62 ; 27.05,145.06 v1(27.05,145.67) ; 27.05,145.06 27.05,144.65 26.29,143.89 20.95,143.89 L6.2
  CONDUCTIVE3 w0.35: 51.58,108.13 50.9,108.62 ; 50.9,108.62 51.7,108.25 ; 50.9,108.62 51.26,107.81 ; 50.9,108.62 48.01,111.51 32.89,111.51 28.07,116.33 28.07,143.13 27.05,144.15 27.05,144.73 ; 50.9,108.62 v1(51.56,107.95) ; 50.9,108.62 51.45,108.01 ; v1(27.05,145.67) 27.05,144.73 ; 27.05,144.73 27.09,145.55 ; 27.05,144.73 26.74,145.55 ; 27.05,144.73 27.36,145.55 ; 27.05,144.73 26.91,145.55 ; v1(60.07,107.95) 60.07,108.89 ; 60.07,108.89 60.07,109.6 62.87,112.39 75.95,112.39 80.12,116.56 80.12,143.02 78.87,144.27 78.87,144.73 ; 60.07,108.89 60.21,108.07 ; 60.07,108.89 59.76,108.07 ; 60.07,108.89 60.03,108.07 ; 60.07,108.89 60.38,108.07 ; 96.45,188.71 96.93,189.39 ; 96.93,189.39 97.28,189.74 142.24,189.74 144.53,187.45 144.53,118.75 135.25,109.47 83.95,109.47 72.77,98.3 71.94,98.3 ; 96.93,189.39 v1(96.27,188.72) ; 96.93,189.39 96.13,189.03 ; 96.93,189.39 96.57,188.58 ; 96.93,189.39 96.32,188.83 ; 104.78,144.73 104.78,144.38 105.92,143.23 105.92,116.46 102.11,112.65 79.25,112.65 77.09,110.49 67.31,110.49 65.44,108.62 ; 104.78,144.73 104.46,145.55 ; 104.78,144.73 105.09,145.55 ; 104.78,144.73 104.64,145.55 ; 104.78,144.73 v1(104.78,145.67) ; 104.78,144.73 104.81,145.55 ; v1(64.77,107.95) 65.44,108.62 ; 65.44,108.62 64.63,108.25 ; 65.44,108.62 65.07,107.81 ; 65.44,108.62 64.83,108.06 ; 65.44,108.62 64.95,107.94 ; 54.61,108.89 54.57,108.07 ; 54.61,108.89 54.3,108.07 ; 54.61,108.89 54.75,108.07 ; 54.61,108.89 v1(54.61,107.95) ; 54.61,108.89 54.61,110.09 54.1,110.6 54.1,143.23 52.96,144.38 52.96,144.73 ; 54.61,108.89 54.92,108.07 ; 130.68,144.73 130.72,145.55 ; 130.68,144.73 130.37,145.55 ; 130.68,144.73 130.55,145.55 ; 130.68,144.73 v1(130.68,145.67) ; 130.68,144.73 130.99,145.55 ; 130.68,144.73 130.68,144.27 131.83,143.13 131.83,116.46 126.49,111.12 81.15,111.12 77.98,107.95 68.76,107.95 ; 78.87,144.73 78.73,145.55 ; 78.87,144.73 78.91,145.55 ; 78.87,144.73 79.18,145.55 ; 78.87,144.73 78.56,145.55 ; 78.87,144.73 v1(78.87,145.67) ; 52.65,145.55 52.96,144.73 ; 52.96,144.73 53,145.55 ; 52.96,144.73 52.82,145.55 ; 52.96,144.73 53.27,145.55 ; 52.96,144.73 v1(52.96,145.67) ; 67.94,108.26 68.76,107.95 ; 68.76,107.95 67.94,107.81 ; 68.76,107.95 67.94,107.64 ; 68.76,107.95 67.94,107.99 ; 68.76,107.95 v1(67.82,107.95) ; 71.11,97.99 71.94,98.3 ; 71.94,98.3 71.11,98.16 ; 71.94,98.3 v1(70.99,98.3) ; 71.94,98.3 71.11,98.34 ; 71.94,98.3 71.11,98.61
  vias: v2(19.68,158.75) v2(19.68,156.84) v2(19.68,154.94) v2(19.68,153.03) v2(19.68,151.13) v2(21.59,158.75) v2(21.59,156.84) v2(21.59,154.94) v2(21.59,153.03) v2(21.59,151.13) v2(23.5,158.75) v2(23.5,156.84) v2(23.5,154.94) v2(23.5,153.03) v2(23.5,151.13) v2(25.4,158.75) v2(25.4,156.84) v2(25.4,154.94) v2(25.4,153.03) v2(25.4,151.13) v2(27.3,158.75) v2(27.3,156.84) v2(27.3,154.94) v2(27.3,153.03) v2(27.3,151.13) v2(27.3,149.22) v2(27.3,147.32) v2(29.21,149.22) v2(29.21,147.32) v2(45.72,158.75) v2(45.72,156.84) v2(45.72,154.94) v2(45.72,153.03) v2(45.72,151.13) v2(47.62,158.75) v2(47.62,156.84) v2(47.62,154.94) v2(47.62,153.03) v2(47.62,151.13) v2(49.53,158.75) v2(49.53,156.84) v2(49.53,154.94) v2(49.53,153.03) v2(49.53,151.13) v2(51.44,158.75) v2(51.44,156.84) v2(51.44,154.94) v2(51.44,153.03) v2(51.44,151.13) v2(53.34,158.75) v2(53.34,156.84) v2(53.34,154.94) v2(53.34,153.03) v2(53.34,151.13) v2(53.34,149.22) v2(53.34,147.32) v2(55.24,149.22) v2(55.24,147.32) v2(71.75,158.75) v2(71.75,156.84) v2(71.75,154.94) v2(71.75,153.03) v2(71.75,151.13) v2(73.66,158.75) v2(73.66,156.84) v2(73.66,154.94) v2(73.66,153.03) v2(73.66,151.13) v2(75.56,158.75) v2(75.56,156.84) v2(75.56,154.94) v2(75.56,153.03) v2(75.56,151.13) v2(77.47,158.75) v2(77.47,156.84) v2(77.47,154.94) v2(77.47,153.03) v2(77.47,151.13) v2(79.38,158.75) v2(79.38,156.84) v2(79.38,154.94) v2(79.38,153.03) v2(79.38,151.13) v2(79.38,149.22) v2(79.38,147.32) v2(81.28,149.22) v2(81.28,147.32) v2(97.79,158.75) v2(97.79,156.84) v2(97.79,154.94) v2(97.79,153.03) v2(97.79,151.13) v2(99.69,158.75) v2(99.69,156.84) v2(99.69,154.94) v2(99.69,153.03) v2(99.69,151.13) v2(101.6,158.75) v2(101.6,156.84) v2(101.6,154.94) v2(101.6,153.03) v2(101.6,151.13) v2(103.5,158.75) v2(103.5,156.84) v2(103.5,154.94) v2(103.5,153.03) v2(103.5,151.13) v2(105.41,158.75) v2(105.41,156.84) v2(105.41,154.94) v2(105.41,153.03) v2(105.41,151.13) v2(105.41,149.22) v2(105.41,147.32) v2(107.31,149.22) v2(107.31,147.32) v2(123.83,158.75) v2(123.83,156.84) v2(123.83,154.94) v2(123.83,153.03) v2(123.83,151.13) v2(125.73,158.75) v2(125.73,156.84) v2(125.73,154.94) v2(125.73,153.03) v2(125.73,151.13) v2(127.64,158.75) v2(127.64,156.84) v2(127.64,154.94) v2(127.64,153.03) v2(127.64,151.13) v2(129.54,158.75) v2(129.54,156.84) v2(129.54,154.94) v2(129.54,153.03) v2(129.54,151.13) v2(131.44,158.75) v2(131.44,156.84) v2(131.44,154.94) v2(131.44,153.03) v2(131.44,151.13) v2(131.44,149.22) v2(131.44,147.32) v2(133.35,149.22) v2(133.35,147.32)
